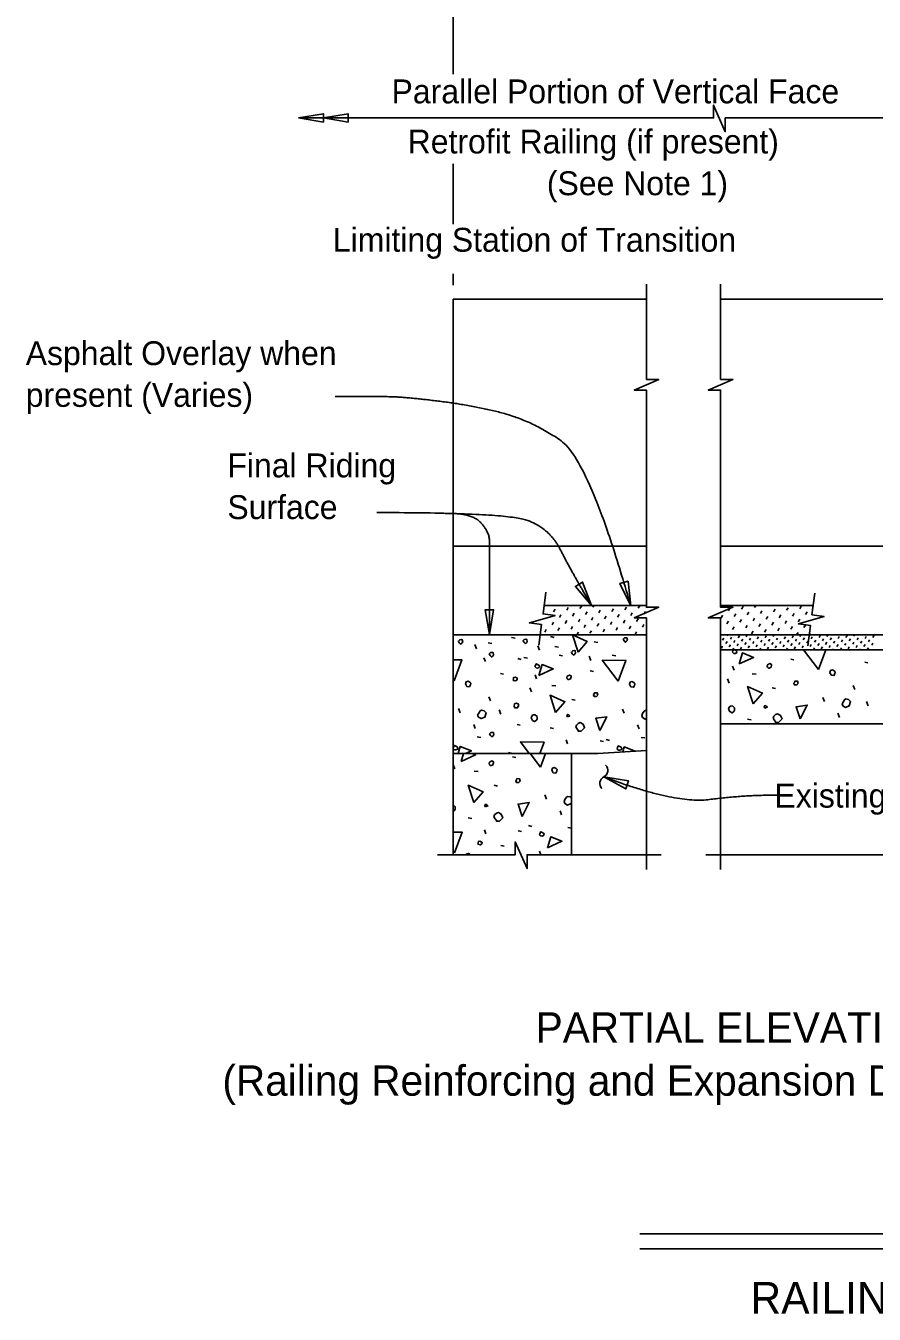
# Model space of a CAD drawing. Extents: x 2.6 to 35.7, y 1.7 to 23.4.
# Drawn here: x 2.62 to 9.78, y 2.18 to 13.05 of the extents above; entities that cross this region are included whole.
import ezdxf

# ---------------------------------------------------------------- set-up
doc = ezdxf.new("R2010")
doc.units = 0
for name, color, linetype in [('Dimension', 7, 'Continuous'), ('Miscellaneous', 7, 'Continuous'), ('SteelMisc_h', 7, 'Continuous'), ('TextStructures', 7, 'Continuous'), ('TrafBarrierConc', 7, 'Continuous')]:
    doc.layers.add(name, color=color, linetype=linetype)

msp = doc.modelspace()

# ---------------------------------------------------------------- linework, layer by layer
at = {"layer": 'Dimension'}
for p, q in [((6.228, 12.644), (6.228, 17.702)), ((6.228, 11.38), (6.228, 11.889)), ((6.228, 10.864), (6.228, 10.96)), ((10.411, 2.859), (7.804, 2.859)), ((10.411, 2.733), (7.804, 2.733))]:
    msp.add_line(p, q, dxfattribs=at)
for points in [[(11.501, 12.276), (8.524, 12.276), (8.524, 12.16), (8.425, 12.385), (8.425, 12.276), (4.925, 12.276)], [(7.859, 9.126), (7.859, 9.979), (7.756, 9.979), (7.859, 10.024), (7.963, 10.069), (7.859, 10.069), (7.859, 10.872)], [(8.485, 9.837), (8.485, 9.979), (8.381, 9.979), (8.485, 10.024), (8.588, 10.069), (8.485, 10.069), (8.485, 10.872)], [(8.485, 5.934), (8.485, 8.057), (8.381, 8.057), (8.485, 8.102), (8.588, 8.147), (8.485, 8.147), (8.485, 9.837)], [(7.859, 5.934), (7.859, 8.057), (7.756, 8.057), (7.859, 8.102), (7.963, 8.147), (7.859, 8.147), (7.859, 9.126)], [(6.952, 7.827), (6.975, 8.001), (6.872, 8.015), (6.981, 8.046), (7.089, 8.077), (6.987, 8.09), (7.011, 8.273)], [(9.22, 7.82), (9.243, 7.994), (9.141, 8.007), (9.249, 8.038), (9.357, 8.069), (9.255, 8.083), (9.279, 8.265)], [(7.984, 6.059), (6.852, 6.059), (6.852, 5.942), (6.753, 6.167), (6.753, 6.059), (6.098, 6.059)], [(12.631, 6.059), (10.067, 6.059), (10.067, 5.942), (9.968, 6.167), (9.968, 6.059), (8.36, 6.059)]]:
    msp.add_lwpolyline(points, dxfattribs=at)
for points in [[(4.925, 12.276), (5.134, 12.241), (5.134, 12.311)], [(5.134, 12.276), (5.342, 12.241), (5.342, 12.311)], [(7.396, 8.162), (7.32, 8.359), (7.26, 8.323)], [(7.727, 8.158), (7.704, 8.367), (7.636, 8.348)], [(6.535, 7.918), (6.57, 8.126), (6.499, 8.126)], [(7.5, 6.716), (7.685, 6.614), (7.708, 6.681)]]:
    msp.add_lwpolyline(points, close=True, dxfattribs=at)
for centre, start, end in [((7.474, 6.77), 295.0115, 46.7387), ((7.525, 6.661), 115.0115, 226.7387)]:
    msp.add_arc(centre, 0.0596, start, end, dxfattribs=at)
for points in [[(5.234, 9.924), (5.536, 9.924), (5.802, 9.924), (6.399, 9.85), (6.888, 9.722), (7.377, 9.391), (7.727, 8.158)], [(5.586, 8.946), (6.669, 8.946), (7.042, 8.814), (7.23, 8.441), (7.396, 8.162)], [(6.161, 8.937), (6.378, 8.946), (6.535, 8.786), (6.535, 8.617), (6.535, 7.918)], [(8.98, 6.561), (8.691, 6.564), (8.103, 6.486), (7.5, 6.716)]]:
    msp.add_open_spline(points, degree=2, dxfattribs=at)
at = {"layer": 'Miscellaneous'}
for p, q in [((7.027, 8.158), (7.031, 8.163)), ((7.298, 8.135), (7.31, 8.157)), ((7.408, 8.148), (7.417, 8.163)), ((7.519, 8.161), (7.52, 8.163)), ((7.789, 8.138), (7.802, 8.16)), ((8.772, 8.144), (8.783, 8.163)), ((8.882, 8.157), (8.886, 8.163)), ((9.152, 8.134), (9.165, 8.156)), ((7.076, 8.109), (7.089, 8.131)), ((7.125, 8.06), (7.138, 8.083)), ((7.187, 8.122), (7.2, 8.144)), ((7.236, 8.073), (7.249, 8.096)), ((7.285, 8.024), (7.298, 8.047)), ((7.346, 8.086), (7.359, 8.108)), ((7.395, 8.037), (7.408, 8.06)), ((7.457, 8.099), (7.47, 8.121)), ((7.506, 8.05), (7.519, 8.073)), ((7.568, 8.112), (7.581, 8.134)), ((7.616, 8.063), (7.629, 8.086)), ((7.678, 8.125), (7.691, 8.147)), ((7.727, 8.076), (7.74, 8.099)), ((7.776, 8.027), (7.789, 8.05)), ((7.838, 8.089), (7.851, 8.111)), ((8.489, 8.056), (8.502, 8.079)), ((8.55, 8.118), (8.563, 8.14)), ((8.599, 8.069), (8.612, 8.092)), ((8.661, 8.131), (8.674, 8.153)), ((8.71, 8.082), (8.723, 8.105)), ((8.759, 8.033), (8.772, 8.056)), ((8.82, 8.095), (8.833, 8.118)), ((8.869, 8.046), (8.882, 8.069)), ((8.931, 8.108), (8.944, 8.13)), ((8.98, 8.059), (8.993, 8.082)), ((9.042, 8.121), (9.055, 8.143)), ((9.091, 8.072), (9.104, 8.095)), ((9.139, 8.023), (9.152, 8.046)), ((9.201, 8.085), (9.214, 8.108)), ((7.001, 7.937), (7.014, 7.959)), ((7.063, 7.998), (7.076, 8.021)), ((7.112, 7.95), (7.125, 7.972)), ((7.174, 8.011), (7.187, 8.034)), ((7.223, 7.962), (7.236, 7.985)), ((7.333, 7.975), (7.346, 7.998)), ((7.382, 7.927), (7.395, 7.949)), ((7.444, 7.988), (7.457, 8.011)), ((7.493, 7.94), (7.506, 7.962)), ((7.555, 8.001), (7.568, 8.024)), ((7.603, 7.953), (7.616, 7.975)), ((7.665, 8.014), (7.678, 8.037)), ((7.714, 7.966), (7.727, 7.988)), ((7.763, 7.917), (7.776, 7.939)), ((7.825, 7.978), (7.838, 8.001)), ((8.537, 8.007), (8.55, 8.03)), ((8.586, 7.959), (8.599, 7.981)), ((8.648, 8.02), (8.661, 8.043)), ((8.697, 7.972), (8.71, 7.994)), ((8.746, 7.923), (8.759, 7.945)), ((8.807, 7.985), (8.82, 8.007)), ((8.856, 7.936), (8.869, 7.958)), ((8.918, 7.997), (8.931, 8.02)), ((8.967, 7.949), (8.98, 7.971)), ((9.029, 8.01), (9.042, 8.033)), ((9.078, 7.962), (9.091, 7.984)), ((9.188, 7.975), (9.201, 7.997)), ((6.425, 7.797), (6.411, 7.833)), ((6.525, 7.847), (6.555, 7.841)), ((6.722, 7.891), (6.752, 7.885)), ((7.05, 7.899), (7.08, 7.893)), ((7.272, 7.914), (7.285, 7.936)), ((7.418, 7.855), (7.448, 7.849)), ((8.501, 7.869), (8.511, 7.886)), ((8.529, 7.841), (8.539, 7.857)), ((8.539, 7.907), (8.543, 7.913)), ((8.557, 7.812), (8.567, 7.829)), ((8.567, 7.879), (8.577, 7.895)), ((8.595, 7.85), (8.605, 7.867)), ((8.624, 7.822), (8.633, 7.839)), ((8.633, 7.888), (8.643, 7.905)), ((8.662, 7.86), (8.671, 7.877)), ((8.69, 7.832), (8.7, 7.849)), ((8.7, 7.898), (8.709, 7.913)), ((8.728, 7.87), (8.738, 7.887)), ((8.756, 7.842), (8.766, 7.858)), ((8.766, 7.908), (8.769, 7.913)), ((8.785, 7.813), (8.794, 7.83)), ((8.794, 7.88), (8.804, 7.896)), ((8.823, 7.851), (8.832, 7.868)), ((8.851, 7.823), (8.861, 7.84)), ((8.861, 7.889), (8.87, 7.906)), ((8.889, 7.861), (8.899, 7.878)), ((8.917, 7.833), (8.927, 7.849)), ((8.927, 7.899), (8.935, 7.913)), ((8.955, 7.871), (8.965, 7.887)), ((8.983, 7.842), (8.993, 7.859)), ((8.993, 7.909), (8.996, 7.913)), ((9.012, 7.814), (9.021, 7.831)), ((9.021, 7.88), (9.031, 7.897)), ((9.05, 7.852), (9.059, 7.869)), ((9.052, 7.912), (9.052, 7.913)), ((9.078, 7.824), (9.088, 7.841)), ((9.088, 7.89), (9.097, 7.907)), ((9.116, 7.862), (9.126, 7.879)), ((9.126, 7.913), (9.139, 7.935)), ((9.144, 7.834), (9.154, 7.85)), ((9.154, 7.9), (9.162, 7.913)), ((9.182, 7.872), (9.192, 7.888)), ((9.211, 7.843), (9.22, 7.86)), ((9.22, 7.91), (9.223, 7.913)), ((9.237, 7.926), (9.238, 7.927)), ((9.239, 7.815), (9.249, 7.832)), ((9.249, 7.881), (9.258, 7.898)), ((9.277, 7.853), (9.287, 7.87)), ((9.305, 7.825), (9.315, 7.842)), ((9.315, 7.891), (9.325, 7.908)), ((9.343, 7.863), (9.353, 7.88)), ((9.371, 7.834), (9.381, 7.851)), ((9.381, 7.901), (9.389, 7.913)), ((9.409, 7.872), (9.419, 7.889)), ((9.438, 7.844), (9.448, 7.861)), ((9.448, 7.91), (9.449, 7.913)), ((9.466, 7.816), (9.476, 7.833)), ((9.476, 7.882), (9.486, 7.899)), ((9.504, 7.854), (9.514, 7.871)), ((9.532, 7.826), (9.542, 7.842)), ((9.542, 7.892), (9.552, 7.909)), ((9.57, 7.864), (9.58, 7.88)), ((9.599, 7.835), (9.608, 7.852)), ((9.608, 7.902), (9.615, 7.913)), ((9.637, 7.873), (9.646, 7.89)), ((9.665, 7.845), (9.675, 7.862)), ((9.675, 7.911), (9.676, 7.913)), ((9.693, 7.817), (9.703, 7.834)), ((9.703, 7.883), (9.713, 7.9)), ((9.731, 7.855), (9.741, 7.872)), ((9.76, 7.826), (9.769, 7.843)), ((9.769, 7.893), (9.779, 7.91)), ((6.501, 7.688), (6.488, 7.721)), ((6.826, 7.723), (6.855, 7.716)), ((6.958, 7.785), (6.944, 7.821)), ((7.086, 7.815), (7.116, 7.809)), ((7.122, 7.742), (7.152, 7.737)), ((7.122, 7.742), (7.152, 7.737)), ((7.391, 7.697), (7.377, 7.733)), ((7.571, 7.742), (7.601, 7.737)), ((8.491, 7.803), (8.501, 7.819)), ((8.528, 7.788), (8.529, 7.791)), ((8.588, 7.788), (8.595, 7.801)), ((8.652, 7.794), (8.662, 7.811)), ((8.718, 7.804), (8.728, 7.82)), ((8.754, 7.788), (8.756, 7.792)), ((8.815, 7.788), (8.823, 7.802)), ((8.879, 7.795), (8.889, 7.811)), ((8.945, 7.804), (8.955, 7.821)), ((8.981, 7.788), (8.983, 7.793)), ((9.042, 7.788), (9.05, 7.803)), ((9.106, 7.796), (9.116, 7.812)), ((9.173, 7.805), (9.182, 7.822)), ((9.208, 7.788), (9.211, 7.794)), ((9.268, 7.788), (9.277, 7.804)), ((9.333, 7.796), (9.343, 7.813)), ((9.4, 7.806), (9.409, 7.823)), ((9.434, 7.788), (9.438, 7.795)), ((9.495, 7.788), (9.504, 7.804)), ((9.561, 7.797), (9.57, 7.814)), ((9.574, 7.782), (9.572, 7.788)), ((9.627, 7.807), (9.637, 7.824)), ((9.661, 7.788), (9.665, 7.796)), ((9.722, 7.788), (9.731, 7.805)), ((6.775, 7.714), (6.803, 7.707)), ((8.598, 7.616), (8.586, 7.65)), ((9.076, 7.708), (9.102, 7.703)), ((9.702, 7.683), (9.728, 7.678)), ((6.628, 7.589), (6.654, 7.583)), ((6.932, 7.542), (6.92, 7.576)), ((7.385, 7.61), (7.412, 7.605)), ((8.556, 7.506), (8.542, 7.542)), ((8.752, 7.586), (8.784, 7.582)), ((6.89, 7.433), (6.876, 7.468)), ((7.062, 7.488), (7.094, 7.484)), ((8.92, 7.467), (8.948, 7.46)), ((9.618, 7.452), (9.604, 7.487)), ((6.289, 7.256), (6.274, 7.292)), ((6.545, 7.357), (6.531, 7.392)), ((7.23, 7.369), (7.258, 7.362)), ((7.672, 7.253), (7.658, 7.288)), ((9.362, 7.351), (9.348, 7.386)), ((9.73, 7.315), (9.716, 7.351)), ((6.632, 7.245), (6.618, 7.281)), ((8.712, 7.202), (8.742, 7.197)), ((9.488, 7.218), (9.475, 7.252)), ((6.414, 7.124), (6.402, 7.157)), ((6.77, 7.157), (6.795, 7.153)), ((7.046, 7.129), (7.076, 7.123)), ((7.797, 7.12), (7.785, 7.154)), ((6.432, 7.053), (6.462, 7.047)), ((7.194, 6.994), (7.182, 7.028)), ((7.468, 7.021), (7.496, 7.014)), ((7.52, 7.03), (7.548, 7.023)), ((7.815, 7.049), (7.846, 7.044)), ((6.696, 6.92), (6.722, 6.915)), ((6.73, 6.885), (6.757, 6.88)), ((6.243, 6.783), (6.23, 6.816)), ((6.407, 6.763), (6.439, 6.76)), ((6.575, 6.645), (6.603, 6.638)), ((7.017, 6.528), (7.003, 6.563)), ((7.142, 6.395), (7.13, 6.429)), ((6.356, 6.369), (6.386, 6.364)), ((6.504, 6.235), (6.492, 6.268)), ((6.778, 6.261), (6.806, 6.254)), ((6.865, 6.305), (6.893, 6.298)), ((7.195, 6.289), (7.225, 6.284)), ((6.631, 6.136), (6.658, 6.13)), ((6.969, 6.059), (6.958, 6.088))]:
    msp.add_line(p, q, dxfattribs=at)
for points in [[(6.28, 7.847), (6.291, 7.836), (6.301, 7.843), (6.309, 7.854), (6.305, 7.872), (6.296, 7.874), (6.284, 7.872), (6.273, 7.861), (6.28, 7.847)], [(6.825, 7.851), (6.836, 7.84), (6.846, 7.847), (6.853, 7.858), (6.85, 7.876), (6.841, 7.878), (6.828, 7.876), (6.818, 7.865), (6.825, 7.851)], [(7.282, 7.767), (7.234, 7.913), (7.359, 7.859), (7.282, 7.767)], [(7.67, 7.863), (7.681, 7.852), (7.691, 7.86), (7.698, 7.87), (7.695, 7.888), (7.686, 7.89), (7.673, 7.888), (7.663, 7.877), (7.67, 7.863)], [(6.541, 7.739), (6.551, 7.728), (6.562, 7.735), (6.569, 7.746), (6.565, 7.764), (6.556, 7.765), (6.544, 7.764), (6.533, 7.753), (6.541, 7.739)], [(7.233, 7.755), (7.244, 7.744), (7.255, 7.751), (7.262, 7.762), (7.258, 7.78), (7.249, 7.781), (7.237, 7.78), (7.226, 7.769), (7.233, 7.755)], [(7.233, 7.755), (7.244, 7.744), (7.255, 7.751), (7.262, 7.762), (7.258, 7.78), (7.249, 7.781), (7.237, 7.78), (7.226, 7.769), (7.233, 7.755)], [(8.593, 7.788), (8.588, 7.779), (8.584, 7.768), (8.595, 7.757)], [(8.595, 7.757), (8.607, 7.756), (8.62, 7.761), (8.623, 7.772), (8.618, 7.78), (8.607, 7.787), (8.605, 7.788)], [(8.641, 7.669), (8.669, 7.761), (8.763, 7.724), (8.641, 7.669)], [(9.311, 7.621), (9.184, 7.788)], [(9.373, 7.788), (9.311, 7.621)], [(6.228, 7.702), (6.303, 7.702), (6.237, 7.527)], [(6.929, 7.635), (6.941, 7.633), (6.954, 7.639), (6.957, 7.649), (6.952, 7.658), (6.941, 7.665), (6.929, 7.67), (6.922, 7.656), (6.918, 7.646), (6.929, 7.635)], [(6.951, 7.571), (6.979, 7.663), (7.073, 7.626), (6.951, 7.571)], [(7.621, 7.523), (7.486, 7.7), (7.686, 7.698), (7.621, 7.523)], [(8.888, 7.634), (8.895, 7.634), (8.91, 7.641), (8.915, 7.657), (8.913, 7.665), (8.899, 7.673), (8.881, 7.662), (8.878, 7.651), (8.881, 7.641), (8.888, 7.634)], [(9.41, 7.589), (9.419, 7.574), (9.44, 7.57), (9.449, 7.586), (9.452, 7.6), (9.443, 7.609), (9.428, 7.618), (9.412, 7.612), (9.406, 7.597), (9.41, 7.589)], [(6.237, 7.527), (6.228, 7.538)], [(6.336, 7.495), (6.345, 7.479), (6.366, 7.476), (6.375, 7.491), (6.379, 7.506), (6.37, 7.514), (6.354, 7.523), (6.338, 7.518), (6.333, 7.502), (6.336, 7.495)], [(6.736, 7.53), (6.755, 7.525), (6.768, 7.534), (6.769, 7.546), (6.766, 7.55), (6.752, 7.557), (6.739, 7.555), (6.738, 7.543), (6.736, 7.53)], [(7.198, 7.536), (7.205, 7.536), (7.219, 7.543), (7.225, 7.559), (7.223, 7.567), (7.209, 7.575), (7.191, 7.564), (7.187, 7.553), (7.191, 7.543), (7.198, 7.536)], [(7.72, 7.491), (7.728, 7.476), (7.75, 7.472), (7.758, 7.488), (7.762, 7.502), (7.753, 7.511), (7.737, 7.52), (7.721, 7.514), (7.716, 7.498), (7.72, 7.491)], [(9.108, 7.492), (9.129, 7.492), (9.139, 7.503), (9.134, 7.522), (9.111, 7.524), (9.108, 7.513), (9.102, 7.505), (9.108, 7.492), (9.104, 7.496)], [(7.093, 7.258), (7.046, 7.404), (7.171, 7.35), (7.093, 7.258)], [(7.417, 7.394), (7.438, 7.394), (7.449, 7.405), (7.444, 7.424), (7.421, 7.426), (7.417, 7.415), (7.412, 7.407), (7.417, 7.394), (7.414, 7.398)], [(8.759, 7.331), (8.712, 7.478), (8.837, 7.423), (8.759, 7.331)], [(6.742, 7.312), (6.75, 7.297), (6.77, 7.298), (6.779, 7.311), (6.78, 7.33), (6.768, 7.335), (6.759, 7.337), (6.749, 7.334), (6.745, 7.33), (6.742, 7.312)], [(8.552, 7.287), (8.563, 7.266), (8.581, 7.255), (8.595, 7.266), (8.602, 7.277), (8.602, 7.298), (8.586, 7.314), (8.567, 7.312), (8.558, 7.303), (8.552, 7.287)], [(8.858, 7.296), (8.878, 7.305), (8.871, 7.312), (8.858, 7.317), (8.853, 7.305), (8.858, 7.296)], [(9.155, 7.204), (9.122, 7.308), (9.215, 7.321), (9.155, 7.204)], [(9.516, 7.314), (9.539, 7.301), (9.569, 7.314), (9.581, 7.351), (9.564, 7.368), (9.541, 7.374), (9.53, 7.367), (9.518, 7.347), (9.509, 7.331), (9.516, 7.314)], [(6.442, 7.219), (6.465, 7.207), (6.495, 7.219), (6.508, 7.256), (6.49, 7.274), (6.467, 7.279), (6.456, 7.272), (6.444, 7.253), (6.435, 7.237), (6.442, 7.219)], [(6.886, 7.213), (6.897, 7.192), (6.915, 7.182), (6.929, 7.192), (6.936, 7.203), (6.936, 7.224), (6.92, 7.24), (6.901, 7.238), (6.892, 7.229), (6.886, 7.213)], [(7.192, 7.222), (7.212, 7.231), (7.205, 7.238), (7.192, 7.243), (7.187, 7.231), (7.192, 7.222)], [(7.465, 7.106), (7.431, 7.21), (7.525, 7.223), (7.465, 7.106)], [(7.859, 7.274), (7.85, 7.276), (7.84, 7.269), (7.827, 7.249), (7.819, 7.233), (7.826, 7.216)], [(7.826, 7.216), (7.849, 7.203), (7.859, 7.208)], [(8.929, 7.211), (8.952, 7.174), (8.975, 7.176), (8.984, 7.185), (9.003, 7.204), (8.991, 7.234), (8.966, 7.248), (8.948, 7.241), (8.934, 7.227), (8.929, 7.211)], [(6.544, 7.065), (6.554, 7.054), (6.565, 7.061), (6.572, 7.072), (6.568, 7.09), (6.559, 7.091), (6.547, 7.09), (6.536, 7.079), (6.544, 7.065)], [(7.263, 7.137), (7.286, 7.1), (7.309, 7.102), (7.318, 7.111), (7.337, 7.13), (7.325, 7.16), (7.3, 7.175), (7.282, 7.167), (7.268, 7.153), (7.263, 7.137)], [(6.239, 6.945), (6.251, 6.943), (6.264, 6.949), (6.267, 6.959), (6.262, 6.968), (6.251, 6.975), (6.239, 6.981), (6.232, 6.966), (6.228, 6.956)], [(6.271, 6.913), (6.289, 6.973), (6.383, 6.936), (6.333, 6.913)], [(6.87, 6.913), (6.796, 7.01), (6.996, 7.008), (6.961, 6.913)], [(7.622, 6.942), (7.635, 6.94), (7.647, 6.945), (7.651, 6.956), (7.645, 6.965), (7.635, 6.972), (7.622, 6.977), (7.615, 6.963), (7.612, 6.952), (7.622, 6.942)], [(7.659, 6.927), (7.672, 6.969), (7.764, 6.933)], [(6.228, 6.956), (6.239, 6.945)], [(6.386, 6.913), (6.418, 6.901), (6.296, 6.846)], [(6.296, 6.846), (6.316, 6.913)], [(6.966, 6.798), (6.878, 6.913)], [(7.008, 6.913), (6.966, 6.798)], [(6.543, 6.811), (6.55, 6.811), (6.564, 6.818), (6.57, 6.834), (6.568, 6.843), (6.554, 6.85), (6.536, 6.839), (6.532, 6.829), (6.536, 6.818), (6.543, 6.811)], [(7.065, 6.767), (7.073, 6.751), (7.095, 6.747), (7.103, 6.763), (7.107, 6.777), (7.098, 6.786), (7.082, 6.795), (7.066, 6.79), (7.061, 6.774), (7.065, 6.767)], [(6.403, 6.498), (6.356, 6.645), (6.481, 6.59), (6.403, 6.498)], [(6.762, 6.669), (6.783, 6.669), (6.794, 6.68), (6.789, 6.699), (6.766, 6.701), (6.762, 6.691), (6.757, 6.682), (6.762, 6.669), (6.759, 6.673)], [(7.228, 6.536), (7.218, 6.546), (7.195, 6.551), (7.185, 6.544), (7.172, 6.524), (7.164, 6.509), (7.171, 6.491)], [(6.228, 6.425), (6.239, 6.433), (6.246, 6.443), (6.246, 6.464), (6.23, 6.48), (6.228, 6.48)], [(6.502, 6.463), (6.522, 6.471), (6.515, 6.478), (6.502, 6.484), (6.497, 6.471), (6.502, 6.463)], [(6.573, 6.378), (6.596, 6.341), (6.619, 6.342), (6.628, 6.351), (6.647, 6.371), (6.635, 6.401), (6.61, 6.415), (6.593, 6.408), (6.578, 6.394), (6.573, 6.378)], [(6.81, 6.381), (6.776, 6.486), (6.87, 6.498), (6.81, 6.381)], [(7.171, 6.491), (7.194, 6.478), (7.224, 6.491), (7.228, 6.505)], [(6.228, 6.249), (6.306, 6.249), (6.241, 6.074)], [(6.967, 6.217), (6.98, 6.215), (6.992, 6.22), (6.996, 6.231), (6.99, 6.24), (6.98, 6.247), (6.967, 6.252), (6.96, 6.238), (6.957, 6.227), (6.967, 6.217)], [(7.024, 6.118), (7.052, 6.21), (7.146, 6.173), (7.024, 6.118)], [(6.241, 6.074), (6.228, 6.09)], [(6.438, 6.147), (6.458, 6.141), (6.47, 6.15), (6.472, 6.163), (6.468, 6.166), (6.454, 6.173), (6.442, 6.171), (6.44, 6.159), (6.438, 6.147)], [(6.376, 6.059), (6.373, 6.061), (6.357, 6.07), (6.342, 6.065), (6.339, 6.059)]]:
    msp.add_lwpolyline(points, dxfattribs=at)
at = {"layer": 'SteelMisc_h'}
msp.add_line((6.228, 8.888), (6.228, 10.548), dxfattribs=at)
at = {"layer": 'TrafBarrierConc'}
for p, q in [((6.228, 10.747), (6.228, 8.663)), ((7.859, 10.747), (6.228, 10.747)), ((17.457, 10.747), (8.485, 10.747)), ((6.228, 8.663), (6.228, 6.059)), ((6.228, 8.663), (7.859, 8.663)), ((8.485, 8.663), (17.457, 8.663)), ((6.997, 8.163), (7.859, 8.163)), ((8.485, 8.163), (9.266, 8.163)), ((6.228, 7.913), (7.859, 7.913)), ((8.485, 7.913), (17.996, 7.913)), ((8.485, 7.788), (17.996, 7.788)), ((8.485, 7.163), (17.996, 7.163)), ((7.448, 6.913), (6.228, 6.913)), ((7.228, 6.913), (7.228, 6.059)), ((7.448, 6.913), (7.859, 6.939))]:
    msp.add_line(p, q, dxfattribs=at)

# ---------------------------------------------------------------- texts
at = {"layer": 'Dimension'}
for s, height, p in [('Retrofit Railing (if present) ', 0.2016, (5.845, 11.976)), ('(See Note 1)', 0.2016, (7.019, 11.624)), ('Asphalt Overlay when ', 0.2016, (2.623, 10.19)), ('present (Varies)', 0.2016, (2.623, 9.838)), ('Final Riding ', 0.2016, (4.324, 9.243)), ('Surface', 0.2016, (4.324, 8.891)), ('PARTIAL ELEVATION OF INSIDE FACE OF RAILING', 0.256, (6.925, 4.473)), ('(Railing Reinforcing and Expansion Dowel Assemblies not shown for clarity)', 0.256, (4.282, 4.025)), ('RAILING END TREATMENT FOR', 0.2688, (8.736, 2.185))]:
    msp.add_text(s, height=height, dxfattribs=at).set_placement(p)
at = {"layer": 'TextStructures'}
for s, p in [('Parallel Portion of Vertical Face', (5.709, 12.399)), ('Limiting Station of Transition', (5.214, 11.147)), ('Existing End Bent Wing Wall', (8.939, 6.456))]:
    msp.add_text(s, height=0.2016, dxfattribs=at).set_placement(p)

doc.saveas('drawing.dxf')
